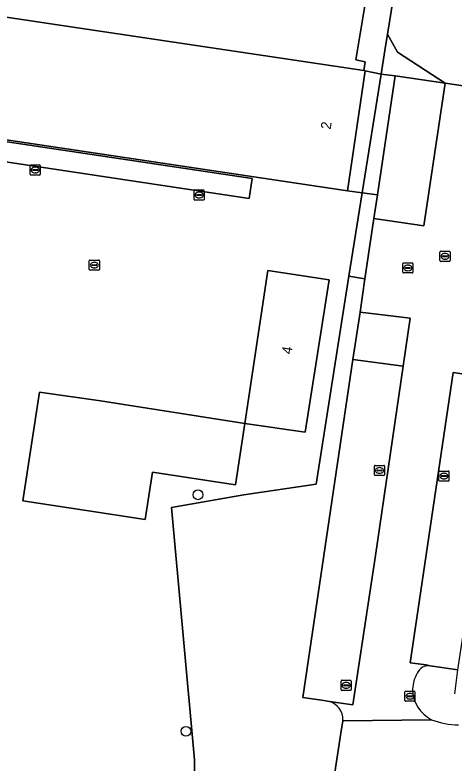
# Model space of a CAD drawing. Extents: x 161090 to 161692, y 379509 to 380907.
# Drawn here: x 161264.8 to 161308.2, y 380179.5 to 380253.5 of the extents above; entities that cross this region are included whole.
import ezdxf

# ---------------------------------------------------------------- set-up
doc = ezdxf.new("R2010")
doc.units = 0
for name, color, linetype in [('IMGEO_Boom', 7, 'Continuous'), ('IMGEO_Erf', 7, 'Continuous'), ('IMGEO_Groenvoorziening', 7, 'Continuous'), ('IMGEO_Hek', 7, 'Continuous'), ('IMGEO_Kolk', 7, 'Continuous'), ('IMGEO_Loofbos', 7, 'Continuous'), ('IMGEO_Pand', 7, 'Continuous'), ('IMGEO_Pand_nummerreeks', 7, 'Continuous'), ('IMGEO_Parkeervlak_gesloten', 7, 'Continuous'), ('IMGEO_Rijbaan_lokaal_gesloten', 7, 'Continuous'), ('IMGEO_Rioolput', 7, 'Continuous'), ('IMGEO_Voetpad_gesloten', 7, 'Continuous'), ('IMGEO_Voetpad_open', 7, 'Continuous')]:
    doc.layers.add(name, color=color, linetype=linetype)

msp = doc.modelspace()

# ---------------------------------------------------------------- linework, layer by layer
at = {"layer": 'IMGEO_Boom'}
for centre in [(161282.853, 380206.062), (161281.668, 380182.662)]:
    msp.add_circle(centre, 0.489, dxfattribs=at)
at = {"layer": 'IMGEO_Erf'}
for points in [[(161252.658, 380254.997), (161268.965, 380252.557), (161299.247, 380248.027), (161299.367, 380248.873), (161298.444, 380249.078), (161299.857, 380257.63)], [(161262.525, 380149.986), (161265.35, 380149.853), (161269.88, 380149.639), (161282.167, 380149.06), (161282.498, 380179.855), (161280.254, 380204.807), (161287.389, 380206.038), (161294.54, 380207.121), (161297.773, 380227.67), (161299.089, 380235.933), (161297.624, 380236.117), (161250.877, 380243.129)]]:
    msp.add_lwpolyline(points, dxfattribs=at)
for points in [[(161251.355, 380240.862), (161251.662, 380242.81), (161288.227, 380237.348), (161287.93, 380235.359)], [(161287.501, 380213.116), (161289.771, 380228.247), (161295.833, 380227.337), (161293.445, 380212.244)], [(161278.356, 380208.299), (161277.649, 380203.599), (161271.615, 380204.522), (161265.54, 380205.451), (161267.188, 380216.225), (161273.225, 380215.353), (161287.501, 380213.116), (161286.903, 380209.207), (161286.573, 380207.047)]]:
    msp.add_lwpolyline(points, close=True, dxfattribs=at)
at = {"layer": 'IMGEO_Groenvoorziening'}
for points in [[(161302.475, 380257.198), (161299.857, 380257.63), (161298.444, 380249.078), (161299.367, 380248.873), (161299.247, 380248.027), (161299.368, 380248.009), (161300.955, 380247.653), (161301.329, 380250), (161301.587, 380251.619), (161301.812, 380253.032)], [(161315.312, 380255.309), (161302.475, 380257.198), (161301.812, 380253.032), (161301.587, 380251.619), (161302.585, 380249.848), (161307.284, 380246.773), (161312.199, 380246.054), (161317.141, 380245.33), (161324.162, 380244.173), (161324.892, 380248.973), (161321.492, 380248.501), (161314.369, 380249.618)], [(161302.585, 380249.848), (161301.587, 380251.619), (161301.329, 380250), (161300.955, 380247.653), (161302.341, 380247.496), (161307.284, 380246.773)]]:
    msp.add_lwpolyline(points, close=True, dxfattribs=at)
at = {"layer": 'IMGEO_Hek'}
for points in [[(161300.955, 380247.653), (161301.329, 380250), (161301.587, 380251.619), (161301.812, 380253.032), (161302.475, 380257.198)], [(161299.089, 380235.933), (161300.955, 380247.653)], [(161297.773, 380227.67), (161299.089, 380235.933)], [(161287.389, 380206.038), (161294.54, 380207.121), (161297.773, 380227.67)], [(161280.254, 380204.807), (161287.389, 380206.038)], [(161282.224, 380153.845), (161282.498, 380179.855), (161280.254, 380204.807)]]:
    msp.add_lwpolyline(points, dxfattribs=at)
at = {"layer": 'IMGEO_Kolk'}
for p, q in [((161266.273, 380237.763), (161266.273, 380238.615)), ((161266.348, 380238.689), (161267.2, 380238.689)), ((161266.761, 380238.469), (161266.786, 380238.469)), ((161267.274, 380238.615), (161267.274, 380237.763)), ((161266.532, 380238.183), (161266.532, 380238.195)), ((161266.97, 380238.146), (161266.572, 380238.146)), ((161266.575, 380238.232), (161266.973, 380238.232)), ((161266.784, 380237.909), (161266.759, 380237.909)), ((161267.016, 380238.195), (161267.016, 380238.183)), ((161267.2, 380237.689), (161266.348, 380237.689)), ((161282.471, 380235.283), (161282.471, 380236.135)), ((161282.546, 380236.209), (161283.398, 380236.209)), ((161282.73, 380235.703), (161282.73, 380235.715)), ((161283.168, 380235.666), (161282.77, 380235.666)), ((161282.773, 380235.752), (161283.171, 380235.752)), ((161282.959, 380235.989), (161282.984, 380235.989)), ((161283.214, 380235.715), (161283.214, 380235.703)), ((161283.472, 380236.135), (161283.472, 380235.283)), ((161283.398, 380235.209), (161282.546, 380235.209)), ((161282.982, 380235.429), (161282.957, 380235.429)), ((161272.109, 380228.348), (161272.109, 380229.2)), ((161272.184, 380229.274), (161273.036, 380229.274)), ((161272.597, 380229.054), (161272.622, 380229.054)), ((161273.11, 380229.2), (161273.11, 380228.348)), ((161303.099, 380228.074), (161303.099, 380228.926)), ((161303.174, 380229), (161304.026, 380229)), ((161304.1, 380228.926), (161304.1, 380228.074)), ((161273.036, 380228.274), (161272.184, 380228.274)), ((161272.368, 380228.768), (161272.368, 380228.78)), ((161272.806, 380228.731), (161272.408, 380228.731)), ((161272.411, 380228.817), (161272.809, 380228.817)), ((161272.62, 380228.494), (161272.595, 380228.494)), ((161272.852, 380228.78), (161272.852, 380228.768)), ((161303.358, 380228.494), (161303.358, 380228.506)), ((161303.796, 380228.457), (161303.398, 380228.457)), ((161303.401, 380228.543), (161303.799, 380228.543)), ((161303.61, 380228.22), (161303.585, 380228.22)), ((161303.587, 380228.78), (161303.612, 380228.78)), ((161303.842, 380228.506), (161303.842, 380228.494)), ((161304.026, 380228), (161303.174, 380228)), ((161300.294, 380208.038), (161300.294, 380208.89)), ((161300.369, 380208.964), (161301.221, 380208.964)), ((161301.295, 380208.89), (161301.295, 380208.038)), ((161300.553, 380208.458), (161300.553, 380208.47)), ((161300.991, 380208.421), (161300.593, 380208.421)), ((161300.596, 380208.507), (161300.994, 380208.507)), ((161300.805, 380208.184), (161300.78, 380208.184)), ((161300.782, 380208.744), (161300.807, 380208.744)), ((161301.037, 380208.47), (161301.037, 380208.458)), ((161306.662, 380207.482), (161306.662, 380208.334)), ((161306.737, 380208.408), (161307.589, 380208.408)), ((161307.15, 380208.188), (161307.175, 380208.188)), ((161307.663, 380208.334), (161307.663, 380207.482)), ((161301.221, 380207.964), (161300.369, 380207.964)), ((161307.589, 380207.408), (161306.737, 380207.408)), ((161306.921, 380207.902), (161306.921, 380207.914)), ((161307.359, 380207.865), (161306.961, 380207.865)), ((161306.964, 380207.951), (161307.362, 380207.951)), ((161307.173, 380207.628), (161307.148, 380207.628)), ((161307.405, 380207.914), (161307.405, 380207.902)), ((161296.997, 380186.779), (161296.997, 380187.631)), ((161297.072, 380187.705), (161297.924, 380187.705)), ((161297.485, 380187.485), (161297.51, 380187.485)), ((161297.998, 380187.631), (161297.998, 380186.779)), ((161297.924, 380186.705), (161297.072, 380186.705)), ((161297.256, 380187.199), (161297.256, 380187.211)), ((161297.694, 380187.162), (161297.296, 380187.162)), ((161297.299, 380187.248), (161297.697, 380187.248)), ((161297.508, 380186.925), (161297.483, 380186.925)), ((161297.74, 380187.211), (161297.74, 380187.199)), ((161303.301, 380185.704), (161303.301, 380186.556)), ((161303.376, 380186.63), (161304.228, 380186.63)), ((161303.56, 380186.124), (161303.56, 380186.136)), ((161303.998, 380186.087), (161303.6, 380186.087)), ((161303.603, 380186.173), (161304.001, 380186.173)), ((161303.789, 380186.41), (161303.814, 380186.41)), ((161304.044, 380186.136), (161304.044, 380186.124)), ((161304.302, 380186.556), (161304.302, 380185.704)), ((161304.228, 380185.63), (161303.376, 380185.63)), ((161303.812, 380185.85), (161303.787, 380185.85))]:
    msp.add_line(p, q, dxfattribs=at)
for points in [[(161266.273, 380237.763), (161266.273, 380238.615)], [(161266.348, 380238.689), (161267.2, 380238.689)], [(161267.274, 380238.615), (161267.274, 380237.763)], [(161267.2, 380237.689), (161266.348, 380237.689)], [(161282.471, 380235.283), (161282.471, 380236.135)], [(161282.546, 380236.209), (161283.398, 380236.209)], [(161283.472, 380236.135), (161283.472, 380235.283)], [(161283.398, 380235.209), (161282.546, 380235.209)], [(161272.109, 380228.348), (161272.109, 380229.2)], [(161272.184, 380229.274), (161273.036, 380229.274)], [(161273.11, 380229.2), (161273.11, 380228.348)], [(161303.099, 380228.074), (161303.099, 380228.926)], [(161303.174, 380229), (161304.026, 380229)], [(161304.1, 380228.926), (161304.1, 380228.074)], [(161273.036, 380228.274), (161272.184, 380228.274)], [(161304.026, 380228), (161303.174, 380228)], [(161300.294, 380208.038), (161300.294, 380208.89)], [(161300.369, 380208.964), (161301.221, 380208.964)], [(161301.295, 380208.89), (161301.295, 380208.038)], [(161306.662, 380207.482), (161306.662, 380208.334)], [(161306.737, 380208.408), (161307.589, 380208.408)], [(161307.663, 380208.334), (161307.663, 380207.482)], [(161301.221, 380207.964), (161300.369, 380207.964)], [(161307.589, 380207.408), (161306.737, 380207.408)], [(161296.997, 380186.779), (161296.997, 380187.631)], [(161297.072, 380187.705), (161297.924, 380187.705)], [(161297.998, 380187.631), (161297.998, 380186.779)], [(161297.924, 380186.705), (161297.072, 380186.705)], [(161303.301, 380185.704), (161303.301, 380186.556)], [(161303.376, 380186.63), (161304.228, 380186.63)], [(161304.302, 380186.556), (161304.302, 380185.704)], [(161304.228, 380185.63), (161303.376, 380185.63)]]:
    msp.add_lwpolyline(points, dxfattribs=at)
for centre, radius, start, end in [((161266.35, 380238.613), 0.0765, 91.55205, 178.44795), ((161266.35, 380238.613), 0.0765, 91.55205, 178.44795), ((161267.198, 380238.613), 0.0765, 1.55205, 88.44795), ((161267.198, 380238.613), 0.0765, 1.55205, 88.44795), ((161266.35, 380237.765), 0.0765, 181.55205, 268.44795), ((161266.35, 380237.765), 0.0765, 181.55205, 268.44795), ((161266.572, 380238.192), 0.0403, 85.87752, 175.75265), ((161266.569, 380238.182), 0.0366, 178.93798, 274.71019), ((161266.973, 380238.189), 0.043, 264.86636, 352.45326), ((161266.977, 380238.194), 0.0386, 1.73085, 96.63898), ((161267.198, 380237.765), 0.0765, 271.55205, 358.44795), ((161267.198, 380237.765), 0.0765, 271.55205, 358.44795), ((161282.548, 380236.133), 0.0765, 91.55205, 178.44795), ((161282.548, 380236.133), 0.0765, 91.55205, 178.44795), ((161282.77, 380235.712), 0.0403, 85.87752, 175.75265), ((161282.767, 380235.702), 0.0366, 178.93798, 274.71019), ((161283.171, 380235.709), 0.043, 264.86636, 352.45326), ((161283.175, 380235.714), 0.0386, 1.73085, 96.63898), ((161283.396, 380236.133), 0.0765, 1.55205, 88.44795), ((161283.396, 380236.133), 0.0765, 1.55205, 88.44795), ((161282.548, 380235.285), 0.0765, 181.55205, 268.44795), ((161282.548, 380235.285), 0.0765, 181.55205, 268.44795), ((161283.396, 380235.285), 0.0765, 271.55205, 358.44795), ((161283.396, 380235.285), 0.0765, 271.55205, 358.44795), ((161272.186, 380229.198), 0.0765, 91.55205, 178.44795), ((161272.186, 380229.198), 0.0765, 91.55205, 178.44795), ((161273.034, 380229.198), 0.0765, 1.55205, 88.44795), ((161273.034, 380229.198), 0.0765, 1.55205, 88.44795), ((161303.176, 380228.924), 0.0765, 91.55205, 178.44795), ((161303.176, 380228.924), 0.0765, 91.55205, 178.44795), ((161304.024, 380228.924), 0.0765, 1.55205, 88.44795), ((161304.024, 380228.924), 0.0765, 1.55205, 88.44795), ((161272.186, 380228.35), 0.0765, 181.55205, 268.44795), ((161272.186, 380228.35), 0.0765, 181.55205, 268.44795), ((161272.408, 380228.777), 0.0403, 85.87752, 175.75265), ((161272.405, 380228.767), 0.0366, 178.93798, 274.71019), ((161272.809, 380228.774), 0.043, 264.86636, 352.45326), ((161272.813, 380228.779), 0.0386, 1.73085, 96.63898), ((161273.034, 380228.35), 0.0765, 271.55205, 358.44795), ((161273.034, 380228.35), 0.0765, 271.55205, 358.44795), ((161303.398, 380228.503), 0.0403, 85.87752, 175.75265), ((161303.395, 380228.493), 0.0366, 178.93798, 274.71019), ((161303.799, 380228.5), 0.043, 264.86636, 352.45326), ((161303.803, 380228.505), 0.0386, 1.73085, 96.63898), ((161303.176, 380228.076), 0.0765, 181.55205, 268.44795), ((161303.176, 380228.076), 0.0765, 181.55205, 268.44795), ((161304.024, 380228.076), 0.0765, 271.55205, 358.44795), ((161304.024, 380228.076), 0.0765, 271.55205, 358.44795), ((161300.371, 380208.888), 0.0765, 91.55205, 178.44795), ((161300.371, 380208.888), 0.0765, 91.55205, 178.44795), ((161301.219, 380208.888), 0.0765, 1.55205, 88.44795), ((161301.219, 380208.888), 0.0765, 1.55205, 88.44795), ((161300.593, 380208.467), 0.0403, 85.87752, 175.75265), ((161300.59, 380208.457), 0.0366, 178.93798, 274.71019), ((161300.994, 380208.464), 0.043, 264.86636, 352.45326), ((161300.998, 380208.469), 0.0386, 1.73085, 96.63898), ((161306.739, 380208.332), 0.0765, 91.55205, 178.44795), ((161306.739, 380208.332), 0.0765, 91.55205, 178.44795), ((161307.587, 380208.332), 0.0765, 1.55205, 88.44795), ((161307.587, 380208.332), 0.0765, 1.55205, 88.44795), ((161300.371, 380208.04), 0.0765, 181.55205, 268.44795), ((161300.371, 380208.04), 0.0765, 181.55205, 268.44795), ((161301.219, 380208.04), 0.0765, 271.55205, 358.44795), ((161301.219, 380208.04), 0.0765, 271.55205, 358.44795), ((161306.739, 380207.484), 0.0765, 181.55205, 268.44795), ((161306.739, 380207.484), 0.0765, 181.55205, 268.44795), ((161306.961, 380207.911), 0.0403, 85.87752, 175.75265), ((161306.958, 380207.901), 0.0366, 178.93798, 274.71019), ((161307.362, 380207.908), 0.043, 264.86636, 352.45326), ((161307.366, 380207.913), 0.0386, 1.73085, 96.63898), ((161307.587, 380207.484), 0.0765, 271.55205, 358.44795), ((161307.587, 380207.484), 0.0765, 271.55205, 358.44795), ((161297.074, 380187.629), 0.0765, 91.55205, 178.44795), ((161297.074, 380187.629), 0.0765, 91.55205, 178.44795), ((161297.922, 380187.629), 0.0765, 1.55205, 88.44795), ((161297.922, 380187.629), 0.0765, 1.55205, 88.44795), ((161297.074, 380186.781), 0.0765, 181.55205, 268.44795), ((161297.074, 380186.781), 0.0765, 181.55205, 268.44795), ((161297.296, 380187.208), 0.0403, 85.87752, 175.75265), ((161297.293, 380187.198), 0.0366, 178.93798, 274.71019), ((161297.697, 380187.205), 0.043, 264.86636, 352.45326), ((161297.701, 380187.21), 0.0386, 1.73085, 96.63898), ((161297.922, 380186.781), 0.0765, 271.55205, 358.44795), ((161297.922, 380186.781), 0.0765, 271.55205, 358.44795), ((161303.378, 380186.554), 0.0765, 91.55205, 178.44795), ((161303.378, 380186.554), 0.0765, 91.55205, 178.44795), ((161303.6, 380186.133), 0.0403, 85.87752, 175.75265), ((161303.597, 380186.123), 0.0366, 178.93798, 274.71019), ((161304.001, 380186.13), 0.043, 264.86636, 352.45326), ((161304.005, 380186.135), 0.0386, 1.73085, 96.63898), ((161304.226, 380186.554), 0.0765, 1.55205, 88.44795), ((161304.226, 380186.554), 0.0765, 1.55205, 88.44795), ((161303.378, 380185.706), 0.0765, 181.55205, 268.44795), ((161303.378, 380185.706), 0.0765, 181.55205, 268.44795), ((161304.226, 380185.706), 0.0765, 271.55205, 358.44795), ((161304.226, 380185.706), 0.0765, 271.55205, 358.44795)]:
    msp.add_arc(centre, radius, start, end, dxfattribs=at)
for centre, major_axis, ratio, start_param, end_param in [((161266.76, 380238.189), (-0.387, 0.002), 0.722429, 4.712389, 7.853982), ((161266.785, 380238.189), (-0.39, 0.002), 0.717154, 1.570796, 4.712389), ((161282.958, 380235.709), (-0.387, 0.002), 0.722429, 4.712389, 7.853982), ((161282.983, 380235.709), (-0.39, 0.002), 0.717154, 1.570796, 4.712389), ((161272.596, 380228.774), (-0.387, 0.002), 0.722429, 4.712389, 7.853982), ((161272.621, 380228.774), (-0.39, 0.002), 0.717154, 1.570796, 4.712389), ((161303.586, 380228.5), (-0.387, 0.002), 0.722429, 4.712389, 7.853982), ((161303.611, 380228.5), (-0.39, 0.002), 0.717154, 1.570796, 4.712389), ((161300.781, 380208.464), (-0.387, 0.002), 0.722429, 4.712389, 7.853982), ((161300.806, 380208.464), (-0.39, 0.002), 0.717154, 1.570796, 4.712389), ((161307.149, 380207.908), (-0.387, 0.002), 0.722429, 4.712389, 7.853982), ((161307.174, 380207.908), (-0.39, 0.002), 0.717154, 1.570796, 4.712389), ((161297.484, 380187.205), (-0.387, 0.002), 0.722429, 4.712389, 7.853982), ((161297.509, 380187.205), (-0.39, 0.002), 0.717154, 1.570796, 4.712389), ((161303.788, 380186.13), (-0.387, 0.002), 0.722429, 4.712389, 7.853982), ((161303.813, 380186.13), (-0.39, 0.002), 0.717154, 1.570796, 4.712389)]:
    msp.add_ellipse(centre, major_axis=major_axis, ratio=ratio, start_param=start_param, end_param=end_param, dxfattribs=at)
at = {"layer": 'IMGEO_Loofbos'}
for points in [[(161293.208, 380186.002), (161298.175, 380219.442), (161298.872, 380224.139), (161299.359, 380227.417), (161297.773, 380227.67), (161294.54, 380207.121), (161287.389, 380206.038), (161280.254, 380204.807), (161282.498, 380179.855), (161282.167, 380149.06), (161269.88, 380149.639), (161272.221, 380147.991), (161274.8, 380146.749), (161287.27, 380142.328), (161289.136, 380142.691), (161291.111, 380143.774), (161291.529, 380146.508), (161293.197, 380157.657), (161296.972, 380182.47), (161297.167, 380183.699), (161297.183, 380183.797)], [(161295.84, 380185.626), (161295.286, 380185.705), (161293.208, 380186.002)]]:
    msp.add_lwpolyline(points, dxfattribs=at)
msp.add_arc((161295.299, 380183.821), 1.884, 359.25594, 73.32232, dxfattribs=at)
at = {"layer": 'IMGEO_Pand'}
for points in [[(161268.965, 380252.557), (161252.658, 380254.997), (161250.877, 380243.129), (161297.624, 380236.117), (161299.368, 380248.009), (161299.247, 380248.027)], [(161287.501, 380213.116), (161293.445, 380212.244), (161295.833, 380227.337), (161289.771, 380228.247)], [(161278.356, 380208.299), (161286.573, 380207.047), (161286.903, 380209.207), (161287.501, 380213.116), (161273.225, 380215.353), (161267.188, 380216.225), (161265.54, 380205.451), (161271.615, 380204.522), (161277.649, 380203.599)]]:
    msp.add_lwpolyline(points, close=True, dxfattribs=at)
at = {"layer": 'IMGEO_Parkeervlak_gesloten'}
for points in [[(161307.284, 380246.773), (161302.341, 380247.496), (161300.596, 380235.744), (161300.246, 380233.389), (161305.172, 380232.652)], [(161298.872, 380224.139), (161298.175, 380219.442), (161303.119, 380218.778), (161303.81, 380223.53)], [(161303.119, 380218.778), (161298.175, 380219.442), (161293.208, 380186.002), (161295.286, 380185.705), (161295.84, 380185.626), (161298.149, 380185.296), (161300.398, 380200.062)], [(161312.872, 380217.262), (161312.623, 380217.464), (161308.086, 380218.164), (161303.815, 380189.43), (161305.391, 380189.238), (161305.814, 380189.145), (161308.533, 380188.732)]]:
    msp.add_lwpolyline(points, close=True, dxfattribs=at)
at = {"layer": 'IMGEO_Rijbaan_lokaal_gesloten'}
for points in [[(161308.086, 380218.164), (161312.623, 380217.464), (161312.872, 380217.262), (161314.556, 380218.23), (161318.672, 380220.596), (161319.263, 380224.489), (161314.091, 380225.274), (161314.26, 380226.387), (161309.403, 380227.078), (161312.199, 380246.054), (161307.284, 380246.773), (161305.172, 380232.652), (161300.246, 380233.389), (161299.359, 380227.417), (161298.872, 380224.139), (161303.81, 380223.53), (161303.119, 380218.778), (161300.398, 380200.062), (161298.149, 380185.296), (161295.84, 380185.626)], [(161305.814, 380189.145), (161305.391, 380189.238), (161303.815, 380189.43), (161308.086, 380218.164)], [(161305.937, 380183.804), (161297.167, 380183.699), (161296.972, 380182.47), (161293.197, 380157.657), (161291.529, 380146.508), (161291.111, 380143.774), (161291.078, 380143.558), (161290.475, 380140.515), (161288.728, 380134.19), (161285.114, 380126.208), (161282.644, 380121.57), (161277.27, 380114.427), (161282.126, 380110.59), (161284.361, 380113.106), (161286.801, 380116.69), (161288.647, 380119.629), (161289.503, 380120.993), (161289.903, 380121.63)], [(161297.183, 380183.797), (161297.167, 380183.699), (161305.937, 380183.804)]]:
    msp.add_lwpolyline(points, dxfattribs=at)
for centre, radius, start, end in [((161305.665, 380187.903), 1.251, 83.14871, 156.08303), ((161307.609, 380186.653), 3.553, 150.3535, 176.92681), ((161307.482, 380186.857), 3.421, 180.22635, 243.14841), ((161295.299, 380183.821), 1.884, 359.25594, 73.32232), ((161308.837, 380191.679), 8.392, 249.78171, 268.44882)]:
    msp.add_arc(centre, radius, start, end, dxfattribs=at)
at = {"layer": 'IMGEO_Rioolput'}
for p, q in [((161306.771, 380229.222), (161306.771, 380230.074)), ((161306.846, 380230.148), (161307.698, 380230.148)), ((161307.03, 380229.642), (161307.03, 380229.654)), ((161307.468, 380229.605), (161307.07, 380229.605)), ((161307.073, 380229.691), (161307.471, 380229.691)), ((161307.259, 380229.928), (161307.284, 380229.928)), ((161307.514, 380229.654), (161307.514, 380229.642)), ((161307.772, 380230.074), (161307.772, 380229.222)), ((161307.698, 380229.148), (161306.846, 380229.148)), ((161307.282, 380229.368), (161307.257, 380229.368))]:
    msp.add_line(p, q, dxfattribs=at)
for points in [[(161306.771, 380229.222), (161306.771, 380230.074)], [(161306.846, 380230.148), (161307.698, 380230.148)], [(161307.772, 380230.074), (161307.772, 380229.222)], [(161307.698, 380229.148), (161306.846, 380229.148)]]:
    msp.add_lwpolyline(points, dxfattribs=at)
for centre, radius, start, end in [((161306.848, 380230.072), 0.0765, 91.55205, 178.44795), ((161306.848, 380230.072), 0.0765, 91.55205, 178.44795), ((161307.07, 380229.651), 0.0403, 85.87752, 175.75265), ((161307.067, 380229.641), 0.0366, 178.93798, 274.71019), ((161307.471, 380229.648), 0.043, 264.86636, 352.45326), ((161307.475, 380229.653), 0.0386, 1.73085, 96.63898), ((161307.696, 380230.072), 0.0765, 1.55205, 88.44795), ((161307.696, 380230.072), 0.0765, 1.55205, 88.44795), ((161306.848, 380229.224), 0.0765, 181.55205, 268.44795), ((161306.848, 380229.224), 0.0765, 181.55205, 268.44795), ((161307.696, 380229.224), 0.0765, 271.55205, 358.44795), ((161307.696, 380229.224), 0.0765, 271.55205, 358.44795)]:
    msp.add_arc(centre, radius, start, end, dxfattribs=at)
for centre, major_axis, ratio, start_param, end_param in [((161307.258, 380229.648), (-0.387, 0.002), 0.722429, 4.712389, 7.853982), ((161307.283, 380229.648), (-0.39, 0.002), 0.717154, 1.570796, 4.712389)]:
    msp.add_ellipse(centre, major_axis=major_axis, ratio=ratio, start_param=start_param, end_param=end_param, dxfattribs=at)
at = {"layer": 'IMGEO_Voetpad_gesloten'}
msp.add_lwpolyline([(161287.93, 380235.359), (161288.227, 380237.348), (161251.662, 380242.81), (161251.355, 380240.862)], close=True, dxfattribs=at)
at = {"layer": 'IMGEO_Voetpad_open'}
for points in [[(161297.624, 380236.117), (161299.089, 380235.933), (161300.955, 380247.653), (161299.368, 380248.009)], [(161302.341, 380247.496), (161300.955, 380247.653), (161299.089, 380235.933), (161300.596, 380235.744)], [(161300.246, 380233.389), (161300.596, 380235.744), (161299.089, 380235.933), (161297.773, 380227.67), (161299.359, 380227.417)]]:
    msp.add_lwpolyline(points, close=True, dxfattribs=at)
msp.add_lwpolyline([(161308.233, 380186.379), (161308.533, 380188.732), (161305.814, 380189.145)], dxfattribs=at)
for centre, radius, start, end in [((161305.665, 380187.903), 1.251, 83.14871, 156.08303), ((161307.609, 380186.653), 3.553, 150.3535, 176.92681), ((161307.482, 380186.857), 3.421, 180.22635, 243.14841), ((161308.837, 380191.679), 8.392, 249.78171, 268.44882)]:
    msp.add_arc(centre, radius, start, end, dxfattribs=at)

# ---------------------------------------------------------------- texts
at = {"layer": 'IMGEO_Pand_nummerreeks'}
for s, rotation, p in [('2', 81.65686, (161295.962, 380242.154)), ('4', 81.00924, (161292.107, 380219.916))]:
    msp.add_text(s, height=1, rotation=rotation, dxfattribs=at).set_placement(p)

doc.saveas('drawing.dxf')
